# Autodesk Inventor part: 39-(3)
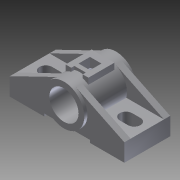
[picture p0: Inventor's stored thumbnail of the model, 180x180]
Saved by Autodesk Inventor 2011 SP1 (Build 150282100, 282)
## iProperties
Created: 2014-02
Part Number: 39-(3)
Document SubType Name: Modeling
Designer: Administrator
Density: 1 g/cm^3
Author: Administrator
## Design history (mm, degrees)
sketch "草图1"
  geometry: L1 (-110, 44)-(110, 44); L2 (110, 44)-(110, -44); L3 (110, -44)-(-110, -44); L4 (-110, -44)-(-110, 44); 3 further points
  constraints: 8 end point, 2 midpoint, 2 parallel, 1 horizontal, 1 horizontal alignment, 1 perpendicular, 1 vertical alignment
  dimensions: "d0" = 220 distance of L1.start L1.end; "d1" = 88 distance of L1.end L2.end
extrude "拉伸1" new body sketch "草图1" distance "d2" = 34; taper "d3" = 0 deg
sketch "草图2"
  geometry: L1 (44, -44)-(-44, -44); L2 (-44, -44)-(-44, 44); L3 (-44, 44)-(44, 44); L4 (44, 44)-(44, -44); 4 further points
  constraints: 8 end point, 3 midpoint, 2 parallel, 1 horizontal, 1 horizontal alignment, 1 perpendicular, 1 vertical alignment
  dimensions: "d4" = 88 distance of L1.start L1.end; "d5" = 88 distance of L1.end L2.end
extrude "拉伸2" cut sketch "草图2" distance "d6" = 5; taper "d7" = 0 deg
sketch "草图3"
  geometry: L1 (110, -44)-(-110, -44) reference; L2 (69, 12)-(85, 12); L3 (69, -12)-(85, -12); A1 r 12 centre (69, 0) between (69, 12) and (69, -12); A2 r 12 centre (85, 0) between (85, -12) and (85, 12); 1 further point
  constraints: 4 end point, 4 point on circle, 2 centre point, 2 parallel, 2 tangent
  dimensions: "d8" = 24 diameter of A1; "d9" = 69 distance of point (0, 0) A1.centre; "d10" = 16 distance of L2.start L2.end
extrude "拉伸3" cut sketch "草图3" stored distance "d11" = 5; taper "d12" = 0 deg
mirror "镜像1"
node "工作平面1"
sketch "草图4"
  geometry: L1 (-110, 0)-(-44, 0) reference; C1 r 39 at (0, 44); 1 further point
  constraints: 1 centre point
  dimensions: "d14" = 78 diameter of C1; "d15" = 44 distance from line of L1 C1.centre
extrude "拉伸4" join sketch "草图4" distance "d17" = 100; taper "d18" = 0 deg
hole "Hole1" diameter "d21" = 56; stored, may be unused: countersink angle "d25" = 90 deg, drill point angle "d27" = 118 deg; dims "d19" = 10, "d20" = 10, "d22" = 6, "d23" = 4, "d24" = 2, "d26" = 8
sketch "草图5"
  geometry: L1 (0, 34)-(-86.983, 76.182); C1 r 39 at (-110, 44) reference; 1 further point
  constraints: 2 end point, 1 tangent
feature "加强筋1" sketch "草图5" dims "d28" = 1, "d29" = 12, "d30" = 0
mirror "镜像2"
mirror "镜像3"
node "工作平面2"
sketch "草图6"
  geometry: L1 (-22, 25)-(22, 25); L2 (22, 25)-(22, -25); L3 (-22, -25)-(-22, 25); L4 (-11, -19)-(11, -19); L5 (11, -19)-(11, -25); L6 (-11, -25)-(-11, -19); L7 (22, -25)-(11, -25); L8 (-11, -25)-(-22, -25); 4 further points
  constraints: 16 end point, 4 parallel, 2 horizontal, 2 midpoint, 2 perpendicular, 1 horizontal alignment, 1 vertical alignment
  dimensions: "d32" = 50 distance of L3.start L1.start; "d33" = 44 distance of L1.start L1.end; "d34" = 6 distance of L4.end L5.end; "d35" = 22 distance of L4.start L4.end
extrude "拉伸5" join sketch "草图6" stored distance "d36" = 100; taper "d37" = 0 deg
sketch "草图7"
  geometry: L1 (-11, 11)-(11, 11); L2 (11, 11)-(11, -11); L3 (11, -11)-(-11, -11); L4 (-11, -11)-(-11, 11); 3 further points
  constraints: 8 end point, 2 midpoint, 2 parallel, 1 horizontal, 1 horizontal alignment, 1 perpendicular, 1 vertical alignment
  dimensions: "d38" = 22 distance of L1.start L1.end; "d39" = 22 distance of L1.end L2.end
extrude "拉伸6" cut sketch "草图7" distance "d40" = 30; taper "d41" = 0 deg
node "实体1"
other parameters: "d31" = 88
